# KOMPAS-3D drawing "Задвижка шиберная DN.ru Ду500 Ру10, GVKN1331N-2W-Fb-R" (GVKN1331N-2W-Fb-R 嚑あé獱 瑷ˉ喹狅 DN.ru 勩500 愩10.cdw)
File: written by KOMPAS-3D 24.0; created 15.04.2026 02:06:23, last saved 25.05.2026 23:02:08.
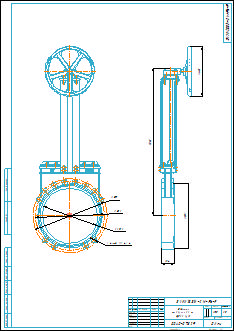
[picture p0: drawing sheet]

Document properties: Автор: DN.ru; Форматы листов документа: A2; Полное имя файла: GVKN1331N-2W-Fb-R Задвижка шиберная DN.ru Ду500 Ру10.m3d; Масса: 195; Наименование: Задвижка шиберная DN.ru Ду500 Ру10; Количество листов документа: 1; Примечание: D040-07829

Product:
- Part/product: Задвижка шиберная DN.ru Ду500 Ру10  | designation GVKN1331N-2W-Fb-R
    Масса: 195
    Раздел спецификации: Прочие изделия
    Примечание: D040-07829

Views: Вид 1, Вид:1, Проекционный вид 2
Referenced files in C:\Работа\GVKN1331N-2W-Fb-R Задвижка шиберная DN.ru Ду400-600 Ру10\DN400\: GVKN1331N-2W-Fb-R Задвижка шиберная DN.ru Ду400 Ру10.m3d
Referenced files in C:\Работа\GVKN1331N-2W-Fb-R Задвижка шиберная DN.ru Ду400-600 Ру10\DN500\: GVKN1331N-2W-Fb-R Задвижка шиберная DN.ru Ду500 Ру10.m3d
Referenced files in C:\Program Files\ASCON\KOMPAS-3D v24\Templates\: Чертеж_DN.ru.cdt
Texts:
  DN500
  GVKN1331N-2W-Fb-R
  Чертеж_DN.ru.cdt
  Задвижка
  шиберная DN.ru
  Ду500 Ру10
  Задвижка шиберная DN.ru Ду500 Ру10
  GVKN1331N-2W-Fb-R Задвижка шиберная DN.ru Ду500 Ру10
Dimensions and other numbers on the sheet: 0; 3; 2; 4; 670; 620; 24 отв.; 24; 1; 1330; 582; 114; 450; 1:5; 195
